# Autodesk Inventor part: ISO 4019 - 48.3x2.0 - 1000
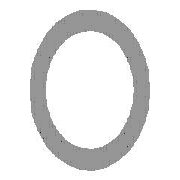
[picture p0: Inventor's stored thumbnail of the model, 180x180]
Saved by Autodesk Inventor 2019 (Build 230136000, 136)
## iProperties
_CCFamilyMember: 14
_CCFamilyDisplayName: ISO 4019 (Profils creux circulaires - Formés à froid) - Aciers de construction - Coupes creuses profilées formées à froid, soudées — ISO 4019 (Profils creux cir
_FrameMemberDoc: Frame Member File
_Version: 15.0.0
_GetPNFromCC: 1
Created: 2018-01
Part Number: ISO 4019 - 48.3x2.0 - 1000
Material: Acier, doux
Description: Aciers de construction - Coupes creuses profilées formées à froid, soudées
Document SubType Name: Modeling
Standard: ISO
Designer: Fabian Perrée
Standard Revision: Second edition 2001-09-01
Standards Organization: ISO
Language: fr-FR
Size Designation: 48.3x2.0
Categories: <MemberInstance><Categories><Category DisplayName="Profilés" InternalName="089c4875-fa83-4c05-b084-43b9cc11f5ed" Mnemonic="GRDR"><CategoryParameter DisplayName=
Stock Number: 48.3x2.0
Density: 7.85 g/cm^3
Appearance: Semi-poli
Mass: 2169.64 g
Surface Area: 2784 cm^2
Volume: 276.387 cm^3
IsCustomPart: 1
G_L: 1000,000 mm
G_W: 48,300 mm
G_H: 48,300 mm
+3083D47D-3926-4B9D-BF58-7B6EDEF830F9+DETAILDECOUPE1: Grugeage
+9EDA2250-0570-480B-9858-EB109F37A463+DETAILDECOUPE2: Grugeage
Author: Fabian Perrée
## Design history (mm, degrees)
node "Plan de départ"
node "Plan de fin"
sketch "Esquisse"
  geometry: C1 r 22.15 at (0, 0); C2 r 24.15 at (0, 0); 2 further points
  constraints: 3 coincident, 2 centre point
  dimensions: "d0" = 48.3 diameter of C2 (= G_H); "d1" = 2 radial gap between concentric circles of C2 C1 (= G_T)
extrude "Corps" new body sketch "Esquisse" stored distance "d2" = 1000 (= G_L); taper "d3" = 0 deg
node "Driven Length"
  sketch "Sketch3"
    geometry: L1 (0, 0)-(10, 0) reference
    constraints: 2 end point, 1 horizontal
  workplane "Work Plane3"
  sketch "Sketch4"
    geometry: L1 (-2, 0)-(12, 0) reference; L2 (-2, 1000)-(12, 1000) reference
    dimensions: "d7" = 1000 distance between parallel lines of L1 L2 (derived)
body "Solid1"
feature "Sculpter1"
feature "Combiner1"
feature "Sculpter3"
feature "Combiner3"
body "Srf23"
body "Srf24"
node "Solide9"
body "Srf26"
body "Srf27"
node "Solide10"
feature "Surface1"
body "Srf22"
feature "Carreau délimité15" dims "d36" = 5, "d37" = 0
feature "Carreau délimité16" dims "d38" = 5, "d39" = 0
feature "Surface3"
body "Srf25"
feature "Carreau délimité17" dims "d40" = 5, "d41" = 0
feature "Carreau délimité18" dims "d42" = 5, "d43" = 0
other parameters: "G_H" = 48.3 [user parameter; used in 1 equation term], "G_T" = 2 [user parameter; used in 1 equation term], "G_L" = 1000 (= d7) [user parameter; used in 1 equation term], "G_OFFSET_START" = 0 [user parameter; used in 1 equation term], "G_OFFSET_END" = 0 [user parameter; used in 1 equation term], "d4" = 0 (computed from G_OFFSET_START), "d5" = 1000 (= G_OFFSET_END + B_L), "B_L" = 1000 [user parameter; used in 1 equation term], "d6" = 90 deg, "MAS" = 0.228 [user parameter]
